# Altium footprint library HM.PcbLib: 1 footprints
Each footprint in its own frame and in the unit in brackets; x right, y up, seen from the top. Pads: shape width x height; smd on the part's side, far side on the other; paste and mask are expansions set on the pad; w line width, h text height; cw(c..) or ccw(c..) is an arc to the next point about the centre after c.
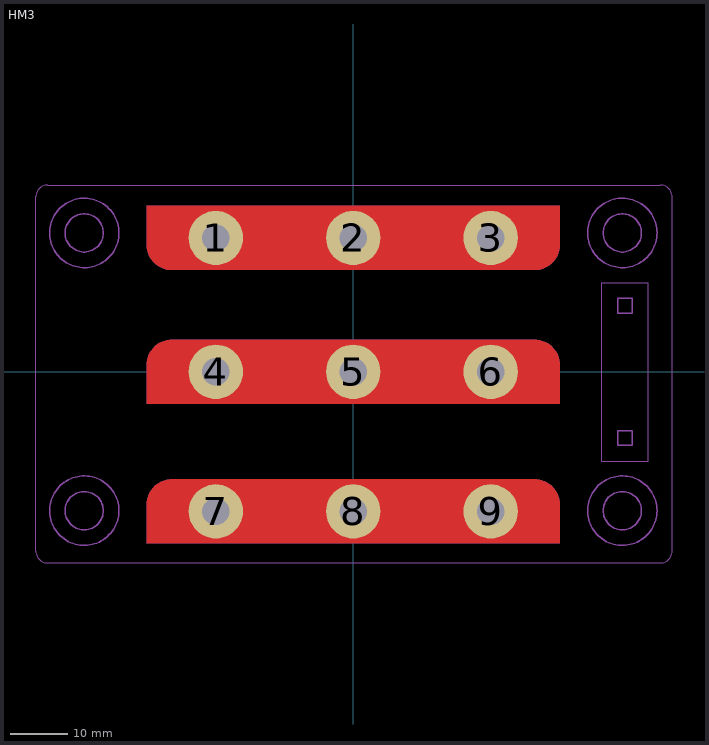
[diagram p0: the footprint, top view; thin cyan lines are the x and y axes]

## HM3 [mm] "HM3 Module"
pads (9):
  round 9.4 hole 4.7: 1(-23.75,23.13) 2(0,23.13) 3(23.75,23.13) 4(-23.75,0) 5(0,0) 6(23.75,0) 7(-23.75,-24.13) 8(0,-24.13) 9(23.75,-24.13)
Top Layer:
  region: -35.65,-29.655 35.65,-29.655 35.65,-22.847 35.65,-22.569 35.577,-22.017 35.434,-21.48 35.221,-20.967 34.943,-20.485 34.604,-20.044 34.211,-19.651 33.77,-19.312 33.288,-19.034 32.775,-18.821 32.238,-18.678 31.686,-18.605 31.408,-18.605 -31.408,-18.605 -31.686,-18.605 -32.238,-18.678 -32.775,-18.821 -33.288,-19.034 -33.77,-19.312 -34.211,-19.651 -34.604,-20.044 -34.943,-20.485 -35.221,-20.967 -35.434,-21.48 -35.577,-22.017 -35.65,-22.569 -35.65,-22.847 -35.65,-24.13
  region: -35.65,-5.525 35.65,-5.525 35.65,1.283 35.65,1.561 35.577,2.113 35.434,2.65 35.221,3.163 34.943,3.645 34.604,4.086 34.211,4.479 33.77,4.818 33.288,5.096 32.775,5.309 32.238,5.452 31.686,5.525 31.408,5.525 -31.408,5.525 -31.686,5.525 -32.238,5.452 -32.775,5.309 -33.288,5.096 -33.77,4.818 -34.211,4.479 -34.604,4.086 -34.943,3.645 -35.221,3.163 -35.434,2.65 -35.577,2.113 -35.65,1.561 -35.65,1.283 -35.65,0
  region: 35.65,28.655 -35.65,28.655 -35.65,21.847 -35.65,21.569 -35.577,21.017 -35.434,20.48 -35.221,19.967 -34.943,19.485 -34.604,19.044 -34.211,18.651 -33.77,18.312 -33.288,18.034 -32.775,17.821 -32.238,17.678 -31.686,17.605 -31.408,17.605 31.408,17.605 31.686,17.605 32.238,17.678 32.775,17.821 33.288,18.034 33.77,18.312 34.211,18.651 34.604,19.044 34.943,19.485 35.221,19.967 35.434,20.48 35.577,21.017 35.65,21.569 35.65,21.847 35.65,23.13
Bottom Layer:
  region: -35.65,-5.525 35.65,-5.525 35.65,1.283 35.65,1.561 35.577,2.113 35.434,2.65 35.221,3.163 34.943,3.645 34.604,4.086 34.211,4.479 33.77,4.818 33.288,5.096 32.775,5.309 32.238,5.452 31.686,5.525 31.408,5.525 -31.408,5.525 -31.686,5.525 -32.238,5.452 -32.775,5.309 -33.288,5.096 -33.77,4.818 -34.211,4.479 -34.604,4.086 -34.943,3.645 -35.221,3.163 -35.434,2.65 -35.577,2.113 -35.65,1.561 -35.65,1.283 -35.65,0
  region: 35.65,28.655 -35.65,28.655 -35.65,21.847 -35.65,21.569 -35.577,21.017 -35.434,20.48 -35.221,19.967 -34.943,19.485 -34.604,19.044 -34.211,18.651 -33.77,18.312 -33.288,18.034 -32.775,17.821 -32.238,17.678 -31.686,17.605 -31.408,17.605 31.408,17.605 31.686,17.605 32.238,17.678 32.775,17.821 33.288,18.034 33.77,18.312 34.211,18.651 34.604,19.044 34.943,19.485 35.221,19.967 35.434,20.48 35.577,21.017 35.65,21.569 35.65,21.847 35.65,23.13
  region: -35.65,-29.655 35.65,-29.655 35.65,-22.847 35.65,-22.569 35.577,-22.017 35.434,-21.48 35.221,-20.967 34.943,-20.485 34.604,-20.044 34.211,-19.651 33.77,-19.312 33.288,-19.034 32.775,-18.821 32.238,-18.678 31.686,-18.605 31.408,-18.605 -31.408,-18.605 -31.686,-18.605 -32.238,-18.678 -32.775,-18.821 -33.288,-19.034 -33.77,-19.312 -34.211,-19.651 -34.604,-20.044 -34.943,-20.485 -35.221,-20.967 -35.434,-21.48 -35.577,-22.017 -35.65,-22.569 -35.65,-22.847 -35.65,-24.13
Top Solder:
  region: -35.65,-5.525 35.65,-5.525 35.65,1.283 35.65,1.561 35.577,2.113 35.434,2.65 35.221,3.163 34.943,3.645 34.604,4.086 34.211,4.479 33.77,4.818 33.288,5.096 32.775,5.309 32.238,5.452 31.686,5.525 31.408,5.525 -31.408,5.525 -31.686,5.525 -32.238,5.452 -32.775,5.309 -33.288,5.096 -33.77,4.818 -34.211,4.479 -34.604,4.086 -34.943,3.645 -35.221,3.163 -35.434,2.65 -35.577,2.113 -35.65,1.561 -35.65,1.283 -35.65,0
  region: -35.65,-29.655 35.65,-29.655 35.65,-22.847 35.65,-22.569 35.577,-22.017 35.434,-21.48 35.221,-20.967 34.943,-20.485 34.604,-20.044 34.211,-19.651 33.77,-19.312 33.288,-19.034 32.775,-18.821 32.238,-18.678 31.686,-18.605 31.408,-18.605 -31.408,-18.605 -31.686,-18.605 -32.238,-18.678 -32.775,-18.821 -33.288,-19.034 -33.77,-19.312 -34.211,-19.651 -34.604,-20.044 -34.943,-20.485 -35.221,-20.967 -35.434,-21.48 -35.577,-22.017 -35.65,-22.569 -35.65,-22.847 -35.65,-24.13
  region: 35.65,28.655 -35.65,28.655 -35.65,21.847 -35.65,21.569 -35.577,21.017 -35.434,20.48 -35.221,19.967 -34.943,19.485 -34.604,19.044 -34.211,18.651 -33.77,18.312 -33.288,18.034 -32.775,17.821 -32.238,17.678 -31.686,17.605 -31.408,17.605 31.408,17.605 31.686,17.605 32.238,17.678 32.775,17.821 33.288,18.034 33.77,18.312 34.211,18.651 34.604,19.044 34.943,19.485 35.221,19.967 35.434,20.48 35.577,21.017 35.65,21.569 35.65,21.847 35.65,23.13
Bottom Solder:
  region: -35.65,-29.655 35.65,-29.655 35.65,-22.847 35.65,-22.569 35.577,-22.017 35.434,-21.48 35.221,-20.967 34.943,-20.485 34.604,-20.044 34.211,-19.651 33.77,-19.312 33.288,-19.034 32.775,-18.821 32.238,-18.678 31.686,-18.605 31.408,-18.605 -31.408,-18.605 -31.686,-18.605 -32.238,-18.678 -32.775,-18.821 -33.288,-19.034 -33.77,-19.312 -34.211,-19.651 -34.604,-20.044 -34.943,-20.485 -35.221,-20.967 -35.434,-21.48 -35.577,-22.017 -35.65,-22.569 -35.65,-22.847 -35.65,-24.13
  region: -35.65,-5.525 35.65,-5.525 35.65,1.283 35.65,1.561 35.577,2.113 35.434,2.65 35.221,3.163 34.943,3.645 34.604,4.086 34.211,4.479 33.77,4.818 33.288,5.096 32.775,5.309 32.238,5.452 31.686,5.525 31.408,5.525 -31.408,5.525 -31.686,5.525 -32.238,5.452 -32.775,5.309 -33.288,5.096 -33.77,4.818 -34.211,4.479 -34.604,4.086 -34.943,3.645 -35.221,3.163 -35.434,2.65 -35.577,2.113 -35.65,1.561 -35.65,1.283 -35.65,0
  region: 35.65,28.655 -35.65,28.655 -35.65,21.847 -35.65,21.569 -35.577,21.017 -35.434,20.48 -35.221,19.967 -34.943,19.485 -34.604,19.044 -34.211,18.651 -33.77,18.312 -33.288,18.034 -32.775,17.821 -32.238,17.678 -31.686,17.605 -31.408,17.605 31.408,17.605 31.686,17.605 32.238,17.678 32.775,17.821 33.288,18.034 33.77,18.312 34.211,18.651 34.604,19.044 34.943,19.485 35.221,19.967 35.434,20.48 35.577,21.017 35.65,21.569 35.65,21.847 35.65,23.13
Mechanical 7:
  lines w0.127: -54.864,-30.988 ccw(c-52.832,-30.988) -52.832,-33.02 -5.334,-33.02 53.086,-33.02 ccw(c53.086,-30.988) 55.118,-30.988 55.118,30.226 ccw(c53.086,30.226) 53.086,32.258 -52.832,32.258 ccw(c-52.832,30.226) -54.864,30.226 -54.864,-30.988
Mechanical 15:
  circle w0.254: c-46.5,24 r6
  circle w0.254: c-46.5,24 r3.3
  circle w0.254: c-46.5,-24 r6
  circle w0.254: c-46.5,-24 r3.3
  circle w0.254: c46.5,-24 r6
  circle w0.254: c46.5,-24 r3.3
  circle w0.254: c46.5,24 r6
  circle w0.254: c46.5,24 r3.3
  lines w0.127: -54.864,-30.988 ccw(c-52.832,-30.988) -52.832,-33.02 -5.334,-33.02 53.086,-33.02 ccw(c53.086,-30.988) 55.118,-30.988 55.118,30.226 ccw(c53.086,30.226) 53.086,32.258 -52.832,32.258 ccw(c-52.832,30.226) -54.864,30.226 -54.864,-30.988 ; 42.94,-15.43 42.94,15.43 46.94,15.43 50.94,15.43 50.94,-15.43 42.94,-15.43
  lines w0.254: 45.67,-12.7 48.21,-12.7 48.21,-10.16 45.67,-10.16 45.67,-12.7 ; 45.67,10.16 45.67,12.7 48.21,12.7 48.21,10.16 45.67,10.16
3D body "HM3.STEP": height 12.21, standoff -5.09, extent -54.845,-32.919 55.155,32.081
